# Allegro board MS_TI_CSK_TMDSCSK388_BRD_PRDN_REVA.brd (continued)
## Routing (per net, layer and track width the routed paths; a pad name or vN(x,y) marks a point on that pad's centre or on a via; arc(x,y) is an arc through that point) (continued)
VCC_3V3: length 182
  TOP w0.102: 47.98,12.27 U7.T25 ; U7.M7 49.86,21.46 49.42,21.46 49.09,21.13 48.72,21.13 48.51,21.34 U7.R7
  TOP w0.152: U7.T28 U7.U27 ; U7.U27 U7.T26 ; U7.U27 47.32,11.34 47.02,11.64 47.02,11.8 v1(47.01,11.81) ; U7.W7 U7.Y7 U7.Y6 U7.W5 ; U7.W5 46.67,22.34 v1(46.95,22.05) ; U7.W5 U7.Y4 ; v1(48.41,11.64) 48.21,11.84 U7.T26 ; U7.T26 47.98,12.27 ; U7.T6 U7.R5 U7.T4 47.7,22.84 v1(47.52,22.66) ; U7.D16 U7.E17 U7.F16 ; U7.M4 U7.L5 U7.M6 U7.M7 50.3,21.02 50.3,20.66 U7.N10 ; U7.R7 U7.T7
  TOP w0.178: R60.1 53.6,32.42 v1(52.94,32.42) ; v1(59.49,39.37) C35.1 60.2,39.99 60.22,40.01 U3.19
  TOP w0.203: v1(39.09,52.62) 38.44,51.98 U1.N7
  TOP w0.254: C45.1 62.72,31.31 62.89,31.15 R62.1 63.58,31.26 63.1,31.75 v1(63.1,31.85) ; C45.1 61.84,31.31 v1(61.78,31.37) ; C45.1 62.47,31.82 62.51,31.86 U5.1 ; v1(53.85,17.28) 53.98,17.15 U7.D16 ; v1(51.46,49.02) 51.46,47.89 51.21,47.63 C23.1 50.81,47.63 50.78,47.6 U2.1 ; U7.R5 48.67,22.34 v1(48.92,22.1) ; C40.1 50.81,34.67 U4.16 ; R85.1 19.39,1.14 v1(14.19,6.34) ; v1(49.02,20.07) 49.24,19.84 U7.N10 U7.N11 ; U7.Y4 45.61,22.84 45.48,22.71 v1(45.49,22.71) ; v1(39.83,33.45) 39.43,33.06 39.43,31.64 39.08,31.29 R59.1 ; U7.T7 48.01,21.37 48.01,21.81 U7.T6 ; v1(49.49,22.71) 49.62,22.84 U7.M4 ; U7.U25 U7.T25
  TOP w0.305: C20.1 v1(50.83,50.67) ; C15.1 v1(50.83,53.09)
  TOP w0.381: R44.1 45.09,36.04 v1(45.09,36.42) ; v1(64.2,27.84) 64.2,26.91 63.31,26.02 R69.1 ; U9.3 68.39,6.61 68,6.22 v1(66.98,6.22) 67.09,6.33 U9.1 ; R42.1 v1(49.33,35.72) 49.73,36.12 U4.16 ; v1(39.83,33.45) 40.09,33.71 R55.1 ; R70.1 R67.1 16.33,26.5 15.65,27.18 v1(14.76,27.18) ; R20.1 57.71,40.43 58.04,40.09 v1(58.04,39.46) 57.79,39.46 R35.1 ; U10.4 37.13,2.45 C67.1 37.13,2.41 R85.1 ; R45.1 v1(47.04,36.42) ; R7.1 v1(28.1,58.04) ; R24.1 47.34,40.57 v1(47.34,40.83) ; C40.1 v1(51.5,34.66) ; R10.1 v1(49.9,49.13) ; MOD1.46 51.38,52.39 51.38,52.39 C15.1 ; R25.1 v1(49.7,40.11) ; R84.1 v1(43.84,0.76) ; C20.1 51.47,51.37 51.78,51.69 MOD1.47 ; v1(41.45,3.05) 41.45,3.08 42.07,3.7 U11.5 ; R29.1 v1(41.13,37.76) 41.13,36.32 R40.1 ; R43.1 v1(43.87,36.42) ; R23.1 v1(42.63,40.83) ; R26.1 v1(44.15,40.82) ; R57.1 v1(66.32,33.22) ; R22.1 v1(45.75,40.84)
  L03_SIG1 w0.102: v1(53.85,17.28) 53.85,17.17 54.14,16.87 55.26,16.87 55.46,17.08
  L03_SIG1 w0.254: 56.29,17.91 56.46,17.91 v1(57.34,18.78)
  L03_SIG1 w0.305: 56.29,17.91 55.46,17.08
  L04_PWR1 w0.305: v1(47.52,22.66) 47.64,22.66 48,23.01 48,26.36 50.14,28.5 50.14,29.39 47.91,31.62 47.91,33.4 47.4,33.91 40.29,33.91 v1(39.83,33.45)
  L05_PWR2 w0.381: 43.84,1.32 43.84,1.31 v1(43.84,0.76)
  L06_SIG2 w0.178: v1(51.5,34.66) 51.5,33.86 v1(52.94,32.42)
  L06_SIG2 w0.254: v1(47.68,53.26) 45.94,54.99 42.6,54.99 40.23,52.62 v1(39.09,52.62)
  BOTTOM w0.178: C80.1 35.9,40.46 U13.39 ; R118.2 57.22,18.67 v1(57.34,18.78) ; C100.1 48.26,22.93 47.99,22.66 v1(47.52,22.66) ; C82.1 36.4,37.85 36.51,37.96 U13.34 ; C81.1 36.17,39.46 U13.37 ; v1(57.21,8.54) 56.67,8 R130.1 56.53,8.61 56.45,8.69 56.45,10.28 R121.1 ; v1(28.31,27.39) 28.52,27.6 28.52,28.77 29.85,30.1 R103.1 ; v1(60.47,36.99) 60.48,36.98 C83.1 61.37,38.38 61.41,38.41 v1(61.41,38.88) ; U12.1 47.82,56.87 C69.1 47.86,57.5 v1(47.8,57.56)
  BOTTOM w0.203: C177.1 54.28,9.68 C176.1 ; C177.1 53.5,9.65 C178.1 ; C177.1 54.26,10.03 v1(54.52,10.3) ; C114.1 49.46,20.02 49.07,20.02 v1(49.02,20.07)
  BOTTOM w0.254: v1(39.09,52.62) 38.73,52.26 R95.1 R96.1 ; v1(53.17,28.02) 52.88,28.31 C91.1 ; v1(41.13,37.76) 40.62,37.76 40.36,38.02 38.97,38.02 38.91,37.96 U13.34 ; v1(41.45,3.05) C189.1 ; v1(45.49,22.71) 45.67,22.71 45.97,23 45.97,23.91 C103.1 C102.1 ; U13.12 v1(58.04,39.46)
  BOTTOM w0.305: C100.1 C101.1 C102.1
  BOTTOM w0.381: v1(35.89,37.13) 35.82,37.06 35.59,37.06 35.83,37.3 C82.1 C81.1 C80.1 ; R91.1 46.41,53.26 v1(47.68,53.26) ; v1(41.05,6.99) 41.29,7.22 R131.1 ; C181.1 v1(66.98,6.22)
  vias: v1(13.36,20.83) v1(13.36,20.19) v1(13.36,19.56) v1(13.42,19.03) v1(13.92,19.61) v1(13.95,19.03) v1(14.46,19.61) v1(14.48,19.03) v1(35.89,36.49)
VCC_5V0: length 39
  TOP w0.203: U1.D8 32.05,53.06 31.27,53.83 ; U1.L1 v2(36.6,47.1)
  TOP w0.254: U1.N3 38.05,49.53 39.73,49.53 39.93,49.33 40.72,49.33 ; U1.A5 U1.B6 ; U1.A5 29.87,50.9 29.54,50.9 ; U1.A5 29.08,50.68 28.81,50.95
  TOP w0.305: U1.E8 32.7,53.21
  TOP w0.381: Q4.8 v1(22.93,36.53) ; 32.7,53.21 v1(32.7,54.54) ; v1(24.54,51.05) 24.76,51.27 C16.1 ; v1(29.87,57.15) 30.34,57.15 C6.1 30.64,56 31.27,55.36 31.27,53.83 ; v1(40.16,50.04) 40.73,49.47 C22.1 40.72,49.33 40.54,49.15 v1(40.54,48.64)
  L03_SIG1 w0.254: v2(36.6,47.1) 37.78,48.28 39.55,48.28 39.91,48.64 v1(40.54,48.64)
  BOTTOM w0.203: U14.12 25.4,34.7 25.05,35.05 C42.1
  BOTTOM w0.254: v1(32.7,54.54) 34.22,54.54 35.21,53.55 R94.1 ; v2(36.6,47.1) 36.32,46.83 C78.1
  BOTTOM w0.381: J4.87 18.26,40.33 18.32,40.39 v1(19.08,40.39) v1(19.84,40.39) v1(20.6,40.39) v1(21.24,40.39) ; C42.1 23.88,35.58 v1(22.93,36.53) ; R88.1 v1(46.28,51.88)
  vias: v1(9.48,56.21) v1(9.48,55.2) v1(9.48,54.18) v1(9.48,53.16) v1(10.11,56.72) v1(10.11,55.7) v1(10.11,54.69) v1(10.11,53.67) v1(19.08,39.62) v1(19.84,41.15) v1(19.84,39.62) v1(20.6,41.15) v1(20.6,39.62) v1(21.24,41.15) v1(21.24,39.62) v1(23.91,51.82) v1(23.91,51.05) v1(24.54,51.82)
VCC_CAM: length 104.3
  TOP w0.152: U7.D12 U7.E13 U7.F12
  TOP w0.254: v1(53.79,19.31) 53.98,19.12 U7.D12 ; U7.G13 U7.G12 52.52,18.8 52.93,18.8 U7.F12
  L04_PWR1 w0.381: v1(68.42,14.04) 67.48,14.99 64.42,14.99 62.4,17 61.86,17 61.25,16.4 v1(61.25,16.26)
  L05_PWR2 w0.381: v1(68.42,14.04) 67.85,13.47 67.85,11.56 60.86,4.57 50.38,4.57 49.55,3.74 41.39,3.74 41.03,3.39 20.65,3.39 11.47,12.56 11.47,22.46 11.21,22.73 9.68,22.73 v1(9.05,23.37) ; v1(53.79,19.31) 53.79,19.14 54.26,18.67 56.16,18.67 56.67,18.16 59.35,18.16 v1(61.25,16.26)
  BOTTOM w0.203: v1(53.79,19.31) 53.94,19.16 C118.1 53.95,18.67 R118.1
  BOTTOM w0.254: v1(9.05,23.37) 10.09,22.33 J4.22
VDD_DDR: length 76.8
  TOP w0.102: 22.32,23.75 22.35,23.72
  TOP w0.152: U7.AH16 U7.AG15 U7.AF16 ; v1(43.33,17.8) 43.48,17.66 U7.AE15 U7.AE16 U7.AF16 ; v1(42.78,16.38) 42.78,16.64 U7.AF16
  TOP w0.178: U6.D2 v1(32.31,22.55) ; C51.1 27.32,24.62 26.53,23.84 26.53,23.29 26.72,23.1 26.72,22.56 v1(26.71,22.55)
  TOP w0.254: v1(44.99,18.37) 44.98,18.36 U7.AB14 ; U7.AB17 U7.AC17 U7.AC18 U7.AB18 U7.AB17 ; U7.AB17 44.98,16.79 v1(44.95,16.81) 44.98,16.84 U7.AB15 ; U7.AB14 44.94,17.8 v1(44.47,17.8) 44.48,17.8 U7.AC15 U7.AB15 ; U7.AB14 U7.AB15
  TOP w0.381: v1(23.02,33.45) 23.02,32.87 v1(27.59,28.3) ; U6.K8 v1(26.71,16.95) ; U8.F1 v1(30.71,13.19) ; U6.B2 v1(33.91,22.55) ; U8.R1 v1(22.71,13.19) ; U8.H9 v1(29.11,5.99) ; U6.H2 v1(29.11,22.55) ; U6.C9 v1(33.11,16.15) ; U6.K2 v1(26.71,22.55) ; U8.A8 v1(34.71,6.79) ; U6.C1 v1(33.11,23.35) ; R72.1 22.16,23.91 22.32,23.75 ; U8.B2 v1(33.91,12.39) ; U8.K8 v1(26.71,6.79) ; U8.R9 v1(22.71,5.99) ; U8.G7 v1(29.51,8.63) ; U6.D9 v1(32.31,16.15) ; C53.1 22.35,23.72 v1(22.71,23.35) U6.R1 ; U6.H9 v1(29.11,16.15) ; U6.N9 v1(24.31,16.15) ; U8.N1 v1(24.31,13.19) ; U8.K2 v1(26.71,12.39) ; U8.D2 v1(32.31,12.39) ; U6.R9 v1(22.71,16.15) ; C52.1 24.41,24.66 24.31,24.57 v1(24.31,23.35) U6.N1 ; U8.C1 v1(33.11,13.19) ; U8.N9 v1(24.31,5.99) ; U8.A1 v1(34.71,13.19) ; U6.A8 v1(34.71,16.95) ; U6.F1 v1(30.71,23.35) ; U8.C9 v1(33.11,5.99) ; U8.D9 v1(32.31,5.99) ; U8.H2 v1(29.11,12.39) ; U8.E9 v1(31.51,5.99) ; U6.G7 v1(29.51,18.85) ; U6.E9 v1(31.51,16.15) ; U6.A1 v1(34.71,23.35)
  L05_PWR2 w0.178: v1(32.31,22.55) v1(33.11,23.35)
  BOTTOM w0.178: U14.2 26.2,29.67 C93.1 27.54,29.24 27.72,29.07 27.72,28.42 v1(27.59,28.3) ; v2(38.43,15.9) C141.1
  BOTTOM w0.203: U14.9 23.72,32.72 23.02,33.43 v1(23.02,33.45) ; C128.2 42.88,16.48 v1(42.78,16.38) ; v1(44.99,18.37) 44.99,18.37 C122.1 C121.2
  BOTTOM w0.254: C127.1 44.45,17.79 v1(44.47,17.8) ; C135.1 34.88,16.79 v1(34.71,16.95) ; C182.1 34.9,6.61 v1(34.71,6.79)
  BOTTOM w0.381: C184.1 29.26,5.85 v1(29.11,5.99) ; C147.1 22.74,16.12 v1(22.71,16.15) ; C185.1 27.35,6.15 v1(26.71,6.79) ; C107.1 35.12,23.35 v1(34.71,23.35) ; v1(33.11,13.19) 33.19,13.27 C162.1 ; v1(29.11,16.15) 29.25,16.02 29.25,15.85 29.38,15.71 C144.1 ; v1(24.31,13.19) 24.81,13.69 C165.1 ; v1(26.71,12.39) 27.35,13.03 C173.1 ; C188.1 22.62,5.89 v1(22.71,5.99) ; v1(33.11,23.35) 33.07,23.4 C105.1 ; v1(33.11,16.15) 33.19,16.07 C143.1 ; v1(26.71,16.95) 27.48,16.19 C145.1 ; C170.1 35.34,13.1 34.81,13.1 v1(34.71,13.19) ; v1(24.31,5.99) 24.52,5.78 C187.1 ; C146.1 24.65,15.59 24.31,15.92 v1(24.31,16.15) ; C163.1 31.29,13.77 v1(30.71,13.19) ; C104.1 30.88,23.91 30.87,23.9 30.87,23.68 30.83,23.64 30.83,23.47 v1(30.71,23.35) ; v1(22.71,13.19) 22.87,13.35 C166.1 ; v1(29.11,22.55) 29.1,22.54 C98.1 ; v1(33.11,5.99) 33.07,5.94 C183.1
  vias: v1(34.15,28.94) v1(34.4,29.45) v1(34.91,28.94) v1(35.17,29.45) v1(35.67,28.94) v1(35.93,29.45) v1(36.44,28.94)
VDD_DDR_VREF: length 67.2
  TOP w0.102: v2(39.35,16.01) 39.81,16.01 39.98,15.84 U7.AL18
  TOP w0.381: U8.M8 v1(25.11,6.79) ; U6.H1 v1(29.11,23.35) ; U6.M8 v1(25.11,16.95) ; U8.H1 v1(29.11,13.19)
  L04_PWR1 w0.381: v1(25.11,6.79) 25.11,9.78 25.48,10.15 27.36,10.15 28.19,10.97 28.19,12.26 v1(29.11,13.19) ; v1(29.11,13.19) 31.14,15.21 38.55,15.21 v2(39.35,16.01) 39.35,16.61 38.43,17.53 36.25,17.53 33.71,20.07 28.73,20.07 28.35,20.45 28.35,22.59 v1(29.11,23.35) 29.11,23.92 27.99,25.05 25.27,25.05 v1(22.67,27.64) ; v1(29.11,13.19) 28.71,13.6 28.47,13.6 v1(25.11,16.95)
  BOTTOM w0.178: U14.5 24.75,30.82 24.52,31.06 24,31.06 23.51,30.56 23.51,30.49 23.17,30.15 C90.1
  BOTTOM w0.203: C132.2 39.88,16.09 39.81,16.01 v2(39.35,16.01)
  BOTTOM w0.381: v1(22.67,27.64) 22.31,28 22.31,29.27 22.69,29.65 C90.1 ; C106.1 29.11,23.8 v1(29.11,23.35) ; C186.1 26.43,5.48 v1(25.11,6.79) ; v1(29.11,13.19) 29.38,13.46 C164.1 ; v1(25.11,16.95) 25.52,16.55 25.58,16.55 26.55,15.58 C142.1
VDDR_VTT: length 22.7
  TOP w0.254: C50.2 17.17,19.57 18.15,19.57 18.32,19.4 RA4.2
  TOP w0.381: RA4.1 RA4.2 RA4.3 RA4.4 ; v1(18.38,15.4) 18.28,15.29 17.71,15.29 17.16,15.84 C49.2 C50.2
  L06_SIG2 w0.254: v1(24.49,30.35) 25,30.35 25.38,30.73 v1(27.33,30.73)
  BOTTOM w0.178: U14.1 27.24,30.82 v1(27.33,30.73) ; C92.1 25.8,29.46 U14.3
  BOTTOM w0.254: v1(21.34,27.39) 21.53,27.2 C97.2
  BOTTOM w0.381: C92.1 25.56,29.22 C94.1 24.46,30.33 v1(24.49,30.35) v1(23.98,30.35) ; v1(18.46,12.62) C169.2 C154.2 18.46,15.32 v1(18.38,15.4) 18.38,15.67 18.51,15.8 18.51,16.15 RA11.1 RA11.2 RA11.3 RA11.4
  vias: v1(19.14,15.68)
BB_PMIC_3V3: length 2.7
  TOP w0.381: R27.2 12.86,40.39 v1(12.09,41.15)
  BOTTOM w0.381: v1(11.33,41.15) 11.27,41.09 J4.88
  vias: v1(10.57,41.91) v1(10.57,41.15) v1(11.33,41.91) v1(12.09,41.91)
BB_VCC3V3: length 1.7
  BOTTOM w0.254: v1(10.52,21.72) 10.63,21.83 J4.20 12.13,21.83
  vias: v1(8.61,21.72) v1(8.61,21.08) v1(9.25,21.72) v1(9.25,21.08) v1(9.88,21.72) v1(9.88,21.08) v1(10.52,21.08)
CC_RST: length 62.4
  TOP w0.102: v1(42.49,5.42) 42.8,5.12 43.15,5.12 43.41,4.85 44.3,4.85 44.45,4.7 44.45,2.96 43.88,2.4
  TOP w0.14: U11.3 43.52,2.08 R84.2 43.88,2.4
  L06_SIG2 w0.102: 57.31,17.26 56.41,17.26 55.48,16.33 55.48,15.83 54.77,15.11 54.46,15.11 54,14.66 52.27,14.66 51.69,15.24 50.85,15.24 50.07,14.46 50.07,14.28 49.74,13.96 49.68,13.96 49.32,13.61 49.32,13.02 49.38,12.96 49.38,9.97 49.96,9.39 49.99,9.39 51.59,7.79
  L06_SIG2 w0.119: v1(70.87,29.19) 70.22,28.54 69.64,28.54 66.56,25.46 65.94,25.46 64.41,25.46 63.59,24.64 62,24.64 60.66,23.29 60.66,20.62 57.31,17.26 ; v1(42.49,5.42) 42.18,5.73 42.18,6.31 42.47,6.6 43.01,6.6 43.73,5.88 43.73,5.45 44.18,5 52.19,5 52.49,5.3 52.49,6.89 51.59,7.79
  BOTTOM w0.14: J3.54 69.41,27.73 v1(70.87,29.19)
CLK32OUT_PMIC: length 48.6
  TOP w0.14: R36.1 64.81,38.65 v1(64.52,38.35) ; R19.2 v1(28.35,41.93)
  L06_SIG2 w0.102: 35.97,46.3 35.15,47.12 32.89,47.12 32.07,46.3
  L06_SIG2 w0.119: 32.07,46.3 32.04,46.27 31.49,46.27 28.35,43.13 v1(28.35,41.93) ; 35.97,46.3 37.9,44.37 50.72,44.37 51.32,43.76 54.65,43.76 56.77,41.63 56.77,37.39 58.23,35.93 60.11,35.93 60.68,36.5 61.77,37.59 63.76,37.59 v1(64.52,38.35)
CLKIN32: length 5.7
  TOP w0.102: 41.48,7.79 U7.AJ31
  TOP w0.14: R82.2 39.97,5.59 40.05,5.68 41.15,5.68 41.5,6.03 41.5,7.77 41.48,7.79
CORE_CVDD: length 99.5
  TOP w0.102: 47.19,18.34 v1(47.25,18.28)
  TOP w0.254: U7.T17 U7.R17 ; U7.T17 U7.T18 ; U7.T17 U7.U17 ; U7.R17 U7.P17 48.98,16.81 v1(49.01,16.85) 48.98,16.88 U7.P15 U7.R15 v1(48.48,16.84) U7.R17 ; U7.Y19 U7.Y20 U7.W20 U7.W19 ; U7.Y19 U7.W19 ; U7.Y19 45.98,15.79 v1(45.94,15.83) ; U7.W13 46.48,18.85 v1(46.51,18.88) 46.55,18.84 U7.V12 ; U7.W13 47.19,18.34 46.98,18.55 U7.V12 ; U7.W13 U7.W14 ; U7.W13 U7.Y13 U7.Y14 U7.W14 ; U7.W14 46.48,17.39 v1(46.51,17.35) 46.96,17.35 U7.V15 ; U7.U17 U7.V17 46.98,16.8 v1(46.95,16.82) ; U7.U17 47.48,16.91 ; U7.V12 U7.U12 ; U7.V12 U7.V11 U7.U11 U7.U12 ; U7.U12 47.48,18.51 v1(47.25,18.28) 47.75,18.28 47.81,18.34 U7.T13 ; 47.48,16.91 U7.U15 U7.V15 ; 47.48,16.91 47.39,16.82 v1(46.95,16.82) ; U7.V15 46.98,16.88 46.95,16.86 v1(46.95,16.82) ; U7.W19 v1(46.84,15.34)
  L06_SIG2 w0.102: v1(49.01,16.85) 49.01,17.45 49.49,17.92 50.81,17.92 50.82,17.92 51.19,17.92 52.02,18.75 54.43,18.75 55.7,20.02 57.22,20.02 58.05,20.85 58.05,24.91 58.82,25.68 59.72,25.68 v1(60.02,25.99)
  BOTTOM w0.102: v1(48.48,16.84) 48.44,16.84 ; 48.11,16.52 C138.1 ; 47.44,16.33 C140.1 ; v1(60.02,25.99) 60.02,26.33 59.85,26.51 59.85,27.5 59.65,27.69 58.09,27.69 57.89,27.48 54.8,27.48 54.42,27.1 48.64,27.1 48.41,26.88 46.51,26.88 46.31,26.67 44.02,26.67 43.68,27.02 43.68,27.49 43.7,27.51 43.7,28.27 43.47,28.5 41.23,28.5 39.65,30.07 38.54,30.07 25.94,42.67 24.54,42.67 22.64,44.58 22.64,48.26 23.65,49.28 R141.2
  BOTTOM w0.203: v1(46.51,17.35) 46.51,17.2 46.26,16.94 C131.1 ; 48.44,16.84 48.11,16.52 ; C137.1 49.01,16.65 v1(49.01,16.85) 49.01,17.01 C125.1 ; 48.44,16.84 48.07,17.22 C126.1 ; C124.1 47.22,18.26 v1(47.25,18.28) ; C129.1 45.52,16.25 v1(45.94,15.83) 45.7,15.59 C153.1 ; v1(46.95,16.82) 47.44,16.33
  BOTTOM w0.254: v1(47.34,30.25) 47.37,30.27 C88.1
  vias: v1(18.83,42.55) v1(18.95,43.82) v1(18.95,43.18) v1(19.59,42.55) v1(20.35,42.55) v1(21.11,42.55) v1(21.49,43.82) v1(21.49,43.05)
CVDD_ARM: length 5.9
  TOP w0.254: v1(50.02,18.87) 49.98,18.83 U7.M13 U7.M14 ; U7.L17 U7.M17 49.98,15.87 50.01,15.84 v1(50.02,15.84) U7.L18 U7.L17 ; U7.L17 U7.K17
  BOTTOM w0.203: C151.1 50.4,15.51 50.07,15.84 v1(50.02,15.84) 49.86,15.68 49.86,15.47 C150.2 ; C113.1 50.07,19.41 50.07,18.92 v1(50.02,18.87) 50.02,18.72 49.74,18.44 C120.1
  vias: v1(23.78,42.29) v1(23.78,41.4)
CVDD_HDVICP: length 10.6
  TOP w0.102: 46.98,13.83 v1(46.99,13.82)
  TOP w0.152: U7.U21 47.4,14.26 47.4,13.87 47.32,13.79 47.01,13.79 v1(46.99,13.82) ; v1(45.97,13.31) 46.48,13.82 U7.W22
  TOP w0.254: U7.V21 U7.U21 U7.U20 U7.V20 U7.V21 ; U7.V21 46.98,13.83 46.96,13.84 U7.W22
  TOP w0.305: 40.66,40.7 40.83,40.7 C39.2
  TOP w0.381: v1(40.29,40.13) 40.29,40.29 40.58,40.58 R21.2 40.66,40.7 40.82,40.54 v1(40.82,40.13)
  L05_PWR2 w0.381: v1(46.99,13.82) 46.76,13.59 46.25,13.59 v1(45.97,13.31)
  BOTTOM w0.102: C41.1 44.96,13.45 45.11,13.31 45.29,13.31 45.3,13.3 45.61,13.3 45.62,13.31 v1(45.97,13.31)
  BOTTOM w0.203: v1(46.99,13.82) 46.99,13.82 C158.1 ; C168.1 46.27,13.31 v1(45.97,13.31)
DDR_PGOOD: length 76.1
  TOP w0.14: v1(27.18,27.31) 26.86,26.99 26.08,26.99 24.7,28.37 13.75,28.37 11.28,25.89 9.51,25.89 9.12,25.5 v1(8.34,25.5) ; U11.6 v1(40.84,4.28)
  L03_SIG1 w0.119: v1(8.34,25.5) 8.34,25.06 8,24.73 8,20.82 9.42,19.41 9.42,14.64 21.79,2.27 37.38,2.27 38.07,2.97 39.53,2.97 v1(40.84,4.28)
  BOTTOM w0.14: v1(27.18,27.31) 27.49,27.62 27.55,27.62 28.1,28.17 28.1,29.34 28.87,30.1 R103.2 28.68,30.14 27.89,30.94 27.89,31.23 27.59,31.52 U14.20
DM388_BT_EN: length 44.5
  TOP w0.102: U7.M1 50.25,24.61 50.25,24.61 50.7,25.06 51.23,25.06 52.09,25.92 52.09,26.74
  TOP w0.14: 52.09,26.74 52.09,28.43 53.1,29.45 53.43,29.45 54.37,30.38 54.37,32.63 54.14,32.86 54.14,35.6 55.55,37.01 55.55,37.97 55.99,38.41 55.99,40.54 55.46,41.06 50.65,41.06 50.42,41.3 v1(49.97,41.3)
  L03_SIG1 w0.119: v1(43.84,53.49) 45.34,53.49 47.61,51.22 47.61,42.89 49.2,41.3 v1(49.97,41.3)
  BOTTOM w0.14: U12.4 44.74,54.97 44.6,54.83 44.6,54.25 v1(43.84,53.49)
DM388_BTMODE[0]: length 48.1
  TOP w0.102: U7.W6 46.6,21.84 v1(46.95,21.48)
  TOP w0.14: v1(40.09,35.46) 40.09,35.03 40.82,34.3 40.9,34.3 41.45,33.74 R55.2
  L03_SIG1 w0.102: 51.71,26.59 51.57,26.45 51.57,25.73 51.26,25.42 50.35,25.42 48.51,23.58 48.51,21.64 48.1,21.23 48.1,20.6 47.75,20.25 47.19,20.25 47.13,20.31 46.95,20.31 46.57,20.69 46.57,21.1 v1(46.95,21.48)
  L03_SIG1 w0.119: 51.71,26.59 52.26,27.15 52.26,34.91 47.46,39.71 42.35,39.71 41.76,40.29 41.76,40.5 41.63,40.63 41.63,41.95 41.21,42.36 40.31,42.36 39.86,41.91 39.86,36.12 40.09,35.9 v1(40.09,35.46)
  BOTTOM w0.14: v1(40.09,35.46) 38.74,35.46 38.74,35.46 38.37,35.46 38.37,35.46 U13.29
DM388_BTMODE[1]: length 21.7
  TOP w0.102: v1(46.96,22.73) 46.85,22.84 U7.W4
  TOP w0.14: R46.1 40.9,35.01 40.51,35.4 40.51,35.63 40.19,35.96 v1(39.35,35.96)
  L03_SIG1 w0.119: v1(41.46,32.56) 40.87,33.15 40.87,33.76 39.35,35.28 v1(39.35,35.96)
  L06_SIG2 w0.102: 42.59,26.59 44.39,24.79 44.9,24.79 v1(46.96,22.73)
  L06_SIG2 w0.119: 42.59,26.59 42.36,26.82 42.36,28.33 42.15,28.55 42.15,31.87 v1(41.46,32.56)
  BOTTOM w0.14: U13.30 v1(39.35,35.96)
DM388_BTMODE[2]: length 34.9
  TOP w0.102: v1(46.95,23.32) 46.94,23.34 U7.W3
  TOP w0.14: SW1.2 38.28,39.4 39.2,38.47 R28.1 39.96,36.93 v1(40.42,36.46)
  L03_SIG1 w0.102: v1(46.95,23.32) 46.95,23.84 49.71,26.59
  L03_SIG1 w0.119: v1(40.42,36.46) 40.42,37.83 40.85,38.25 45.9,38.25 46.49,37.66 46.49,37.5 47.09,36.91 47.25,36.91 47.54,36.62 47.54,35.96 48.87,34.62 49.6,34.62 50.88,33.34 50.88,30.28 51.15,30.01 51.15,28.25 50.88,27.98 50.88,27.69 50.56,27.37 49.95,26.76 49.87,26.76 49.71,26.59
  BOTTOM w0.14: U13.31 v1(40.42,36.46)
DM388_BTMODE[3]: length 24.5
  TOP w0.102: U7.U2 47.48,24.58 49.49,26.59
  TOP w0.14: v1(41.81,36.96) 42.26,36.96 43.21,36.01 43.21,34.88 43.35,34.73 R43.2 43.91,34.73 44.46,34.18 44.46,33.42 44.46,33.42 44.46,32.68 45.13,32.01 45.13,31.35 45.13,31.35 45.13,31.11 46.75,29.49 49.65,29.49 50.4,28.75 50.4,27.5 49.49,26.59
  BOTTOM w0.14: U13.32 v1(41.81,36.96)
DM388_BTMODE[4]: length 39.8
  TOP w0.102: v1(46.95,20.85) 46.48,20.37 U7.W9
  TOP w0.14: v1(48.85,36.68) 48.4,36.68 47.92,37.16 47.92,38.3 48.76,39.13 R33.1
  L03_SIG1 w0.102: 51.32,26.59 50.64,25.92 50.37,25.92 48.32,23.86 48.32,23.84 48.31,23.83 48.31,21.98 47.91,21.58 47.91,21.32 47.9,21.32 47.9,20.69 47.68,20.47 47.67,20.47 47.66,20.46 47.35,20.46 v1(46.95,20.85)
  L03_SIG1 w0.119: v1(48.85,36.68) 50.04,36.68 51.56,35.15 51.7,35.15 52.04,34.82 52.04,27.89 51.97,27.82 51.97,27.24 51.32,26.59
  BOTTOM w0.14: v1(48.85,36.68) 45.21,40.31 43.85,40.31 42.75,41.41 42.75,41.92 42.46,42.21 42.04,42.21 41.15,41.32 38.51,41.32 38.37,41.46 U13.41
DM388_BTMODE[5]: length 36.3
  TOP w0.102: U7.T5 47.79,22.34 v1(47.51,22.06)
  TOP w0.14: v1(40.25,41.75) 40.25,42.61 41.46,43.82 R16.1
  L03_SIG1 w0.102: 50.55,26.59 50.28,26.32 50.18,26.32 47.9,24.04 47.9,22.45 v1(47.51,22.06)
  L03_SIG1 w0.119: 50.55,26.59 51.42,27.47 51.42,27.9 51.6,28.07 51.6,30.19 51.39,30.4 51.39,33.46 49.62,35.23 49.27,35.23 48.09,36.41 48.09,37.54 46.19,39.44 42.31,39.44 41.54,40.2 41.54,40.4 41.4,40.54 41.4,41.85 41.12,42.14 40.64,42.14 v1(40.25,41.75)
  BOTTOM w0.14: v1(40.25,41.75) 38.59,41.75 38.37,41.96 U13.42
DM388_BTMODE[6]: length 33
  TOP w0.102: U7.T3 47.64,23.34 v1(47.52,23.21)
  TOP w0.14: v1(40.96,41.75) 41.28,42.06 41.28,42.54 41.39,42.65 R18.1
  L03_SIG1 w0.102: 50.17,26.59 47.52,23.95 v1(47.52,23.21)
  L03_SIG1 w0.119: 50.17,26.59 51.15,27.58 51.15,27.94 51.38,28.16 51.38,30.1 51.15,30.32 51.15,33.38 49.59,34.95 49.24,34.95 47.82,36.37 47.82,37.5 46.15,39.17 42.27,39.17 41.32,40.11 41.32,40.31 40.96,40.67 v1(40.96,41.75)
  BOTTOM w0.14: v1(40.96,41.75) 40.54,42.17 39.61,42.17 39.56,42.12 38.71,42.12 38.37,42.46 U13.43
DM388_BTMODE[7]: length 31.6
  TOP w0.102: 49.9,26.59 49.61,26.3 49.48,26.3 48.07,24.89 48.07,24.83 47.68,24.44 47.68,24.14 U7.T2
  TOP w0.14: v1(43.34,41.43) 43.34,39.35 43.13,39.13 43.03,39.13 ; R31.1 43.03,39.13 ; 43.03,39.13 43.34,38.83 43.34,37.47 43.87,36.93 44.16,36.93 44.46,36.63 44.46,35.02 44.77,34.71 44.77,33.32 44.75,33.3 44.75,32.8 45.43,32.13 45.43,31.23 46.89,29.77 49.95,29.77 50.64,29.08 50.64,27.34 50,26.69 50,26.69 49.9,26.59
  BOTTOM w0.14: v1(43.34,41.43) 43.04,41.72 43.04,42.04 42.58,42.51 42.26,42.51 41.64,43.12 38.63,43.12 38.47,42.96 U13.44
DM388_BTMODE[8]: length 26
  TOP w0.102: 50.24,26.59 49.74,26.1 49.57,26.1 48.27,24.8 48.27,24.64 U7.T1
  TOP w0.14: R50.1 46.01,34.73 46.14,34.6 46.14,33.38 45.96,33.19 v1(45.96,33.16) 45.96,31.91 47.12,30.75 49.65,30.75 50.88,29.52 50.88,27.24 50.24,26.59
  BOTTOM w0.14: v1(45.96,33.16) 45.96,34.26 45.66,34.56 40.58,34.56 40.49,34.47 39.68,34.47 39.59,34.56 38.74,34.56 38.21,34.03 37.53,34.03 U13.26
DM388_BTMODE[9]: length 32.4
  TOP w0.102: v1(47.53,21.48) 47.53,21.4 47.98,20.94 U7.T8
  TOP w0.14: v1(50.22,35.36) 49.6,34.74 R48.1
  L03_SIG1 w0.102: v1(47.53,21.48) 48.1,22.06 48.1,23.96 50.27,26.12 50.46,26.12 50.94,26.59
  L03_SIG1 w0.119: 50.94,26.59 51.7,27.35 51.7,27.86 51.82,27.98 51.82,33.56 51.23,34.14 50.53,34.84 50.53,35.05 v1(50.22,35.36)
  BOTTOM w0.14: U13.27 38.23,34.46 38.62,34.85 38.77,34.85 38.78,34.86 39.7,34.86 39.8,34.77 40.37,34.77 40.47,34.86 49.73,34.86 v1(50.22,35.36)
DM388_BTMODE[10]: length 41.9
  TOP w0.102: v1(48.93,21.51) 48.92,21.51 48.92,21.51 48.81,21.51 48.49,21.84 U7.R6
  TOP w0.14: v1(47.63,41.53) 47.91,41.24 47.91,39.4 47.65,39.13 R24.2
  L03_SIG1 w0.102: v1(48.93,21.51) 49.48,21.51 49.88,21.91 49.88,23.74 51.15,25.01 51.44,25.01 52,25.57 52,26.12 52.47,26.59
  L03_SIG1 w0.119: 52.47,26.59 52.78,26.9 52.78,30.89 52.98,31.09 53.22,31.09 53.43,31.29 53.43,34.58 52.04,35.97 51.9,35.97 48.42,39.45 48.42,40.74 v1(47.63,41.53)
  L06_SIG2 w0.119: v1(47.63,41.53) 47.19,41.53 43.37,37.71 43.37,37.12 v1(43.06,36.81)
  BOTTOM w0.14: U13.28 38.31,34.96 38.5,35.15 38.56,35.15 38.57,35.16 39.82,35.16 39.92,35.06 40.25,35.06 40.35,35.16 40.59,35.16 40.85,35.16 42.5,36.81 v1(43.06,36.81)
DM388_BTMODE[11]: length 37.8
  TOP w0.102: v1(48.93,22.72) 48.81,22.84 U7.R4
  TOP w0.14: v1(52.94,31.78) 52.94,31.35 53.04,31.24 53.76,31.24 R60.2
  L06_SIG2 w0.102: v1(48.93,22.72) 48.56,23.09 48.56,23.45 48.99,23.88 51.64,23.88 51.73,23.79 53.29,23.79 56.03,26.53 56.03,26.59
  L06_SIG2 w0.119: 56.03,26.59 56.07,26.63 56.07,28.27 55.65,28.69 55.65,30.16 55.29,30.52 54.69,30.52 53.43,31.78 v1(52.94,31.78) 52.51,31.78 49.65,34.63 42.84,34.63 40.01,37.46 v1(39.2,37.46)
  BOTTOM w0.14: v1(52.94,31.78) 52.94,31.44 53.12,31.26 R60.2 ; v1(39.2,37.46) 38.45,37.46 38.45,37.46 U13.33
DM388_BTMODE[12]: length 33.9
  TOP w0.102: v1(48.94,23.29) 48.89,23.34 U7.R3
  TOP w0.14: v1(42.02,40.79) 42.02,40.31 41.16,39.45 R29.2
  L03_SIG1 w0.102: 52.09,26.59 51.77,26.27 51.77,25.63 51.35,25.21 50.43,25.21 48.94,23.72 v1(48.94,23.29)
  L03_SIG1 w0.119: v1(42.02,40.79) 42.02,40.35 42.39,39.98 47.5,39.98 51.79,35.69 51.93,35.69 52.51,35.11 52.51,27.02 52.09,26.59
  BOTTOM w0.14: v1(42.02,40.79) 41.56,40.79 41.32,41.04 38.45,41.04 38.37,40.96 U13.40
DM388_BTMODE[13]: length 31.5
  TOP w0.102: U7.R2 48.49,23.84 48.77,24.13 48.77,24.3 48.79,24.32 48.79,24.62 49.81,25.64 50.07,25.64 50.96,26.53 51.22,26.53 51.36,26.67
  TOP w0.14: v1(45.16,41.38) 45.16,37.54 46.45,36.24 46.45,35.28 47.01,34.73 R45.2 47.08,34.73 47.64,34.18 47.64,32.98 47.61,32.95 47.61,31.61 47.92,31.29 50.12,31.29 51.36,30.05 51.36,26.67
  BOTTOM w0.14: U13.45 42.47,43.46 44.56,41.38 v1(45.16,41.38)
DM388_BTMODE[14]: length 32
  TOP w0.102: U7.R1 48.48,24.72 49.6,25.84 49.91,25.84 50.66,26.59
  TOP w0.14: 44.69,39.12 44.74,39.12 44.86,39 44.86,37.42 46.16,36.12 46.16,35.02 46.45,34.73 46.45,31.83 47.24,31.04 49.94,31.04 51.12,29.86 51.12,27.05 50.66,26.59 ; 44.69,39.12 R26.2 ; 44.69,39.12 44.83,39.27 44.83,40.97 44.48,41.33 v1(44.48,42.37)
  BOTTOM w0.14: v1(44.48,42.37) 42.89,43.96 U13.46
DM388_BTMODE[15]: length 33.6
  TOP w0.102: U7.P2 48.98,24.22 48.99,24.24 48.99,24.54 49.88,25.43 50.19,25.43 51.03,26.26
  TOP w0.14: 46.24,39.15 46.66,38.72 46.66,37.35 47.08,36.93 47.09,36.93 47.1,36.92 47.36,36.92 47.93,36.35 47.93,32.75 47.9,32.72 47.9,31.73 48.06,31.57 50.19,31.57 51.6,30.16 51.6,26.4 51.46,26.26 51.03,26.26 ; 46.24,39.15 46.44,39.35 v1(46.44,41.4) ; 46.24,39.15 R30.1
  BOTTOM w0.14: U13.47 40.8,44.46 40.87,44.39 41.29,44.39 41.36,44.46 43.38,44.46 v1(46.44,41.4)
DM388_CAM_DAT0: length 42.5
  TOP w0.102: 53.77,26.59 53.77,26.56 54.09,26.24 54.43,26.24 54.77,25.9 54.77,24.14 U7.C2
  TOP w0.14: v1(55.04,29.25) 55.04,28.72 54.47,28.16 53.97,28.16 53.74,27.93 53.74,26.63 53.77,26.59
  L03_SIG1 w0.119: v1(55.04,29.25) 55.04,29.5 54.56,29.98 54.56,30.2 54.18,30.58 54.18,34.88 54.61,35.31 56.05,35.31 56.55,35.8 56.55,35.97 56.11,36.41 56.11,36.58 56.28,36.75 56.45,36.75 56.89,36.31 57.06,36.31 57.22,36.48 57.22,36.65 56.79,37.08 56.79,37.25 56.96,37.42 57.13,37.42 57.56,36.98 57.73,36.98 57.87,37.12 57.87,37.63 57.99,37.75 62.72,37.75 63.25,37.22 63.48,37.22 64.5,37.22 65.76,38.48 68.32,38.48 69.48,39.64 69.81,39.64 70.18,39.26 70.18,39.02 70.34,38.86 71.27,38.86 71.91,39.5 71.91,40.33 72.42,40.84 73.83,40.84 v1(74.26,41.26)
  BOTTOM w0.14: v1(74.26,41.26) 73.79,41.73 J3.1
DM388_CAM_DAT1: length 41.7
  TOP w0.102: 53.46,26.59 53.48,26.58 53.48,26.57 54.01,26.04 54.35,26.04 54.48,25.91 U7.C1
  TOP w0.14: 53.46,26.59 52.68,27.38 52.68,27.77 52.68,28.19 53.25,28.76 53.75,28.76 v1(54.4,29.41)
  L03_SIG1 w0.119: v1(73.39,41.23) 72.26,41.23 71.41,40.38 69.91,40.38 69.21,39.68 66,39.68 65.71,39.39 65.71,38.81 64.39,37.49 63.37,37.49 62.83,38.03 56.27,38.03 56.09,37.85 56.09,37.06 55.91,36.88 53.6,36.88 53.45,36.73 53.45,36.49 53.57,36.37 55.31,36.37 55.43,36.25 55.43,36.01 55.31,35.89 54.03,35.89 53.91,35.77 53.91,30.47 54.34,30.04 54.34,29.89 54.39,29.84 54.39,29.42 v1(54.4,29.41)
  BOTTOM w0.14: J3.3 73.38,41.23 v1(73.39,41.23)
DM388_CAM_DAT2: length 41.5
  TOP w0.102: 55.45,26.63 55.45,26.21 54.99,25.75 54.99,24.23 54.98,24.22 U7.B2
  TOP w0.14: v1(55.05,30.1) 55.45,29.7 55.45,26.63
  L03_SIG1 w0.119: v1(75.26,39.73) 75.26,40.5 75.14,40.62 73.72,40.62 72.51,40.62 72.13,40.24 72.13,39.41 71.37,38.64 70.7,38.64 70.3,38.24 65.87,38.24 65.14,37.52 65.14,36.87 64.91,36.64 63.64,36.64 62.96,36.64 62.12,37.48 59.86,37.48 58.65,36.28 57.34,36.28 56.01,34.95 56.01,34.49 55.84,34.32 55.34,34.32 55.22,34.44 55.22,34.88 55.08,35.03 54.64,35.03 54.45,34.84 54.45,30.69 v1(55.05,30.1)
  BOTTOM w0.14: v1(75.26,39.73) 74.26,40.73 J3.5
DM388_CAM_DAT3: length 41.5
  TOP w0.102: 55.71,26.09 55.2,25.58 55.2,24.1 55.46,23.84 U7.A2
  TOP w0.14: v1(55.1,30.96) 55.71,30.35 55.71,26.09
  L03_SIG1 w0.119: v1(55.1,30.96) 55.54,30.96 55.63,31.06 55.63,31.57 55.53,31.67 54.93,31.67 54.78,31.83 54.78,32.81 55.12,33.14 55.12,33.31 54.84,33.59 54.84,33.76 55.01,33.92 55.18,33.92 55.45,33.65 55.62,33.65 55.99,34.01 56.16,34.01 56.39,33.78 56.56,33.78 56.73,33.94 56.73,34.11 56.34,34.5 56.34,34.67 56.51,34.84 56.68,34.84 57.07,34.45 57.24,34.45 57.41,34.62 57.41,34.79 57.02,35.18 57.02,35.35 57.14,35.47 57.34,35.47 57.74,35.08 57.92,35.08 58.07,35.24 58.07,35.4 57.76,35.71 57.76,35.88 57.87,35.98 60.5,35.98 61.34,36.83 62.23,36.83 62.68,36.38 65.25,36.38 65.36,36.5 65.36,37.43 65.93,37.99 70.46,37.99 70.88,38.42 71.46,38.42 71.62,38.58 72.38,38.58 72.5,38.7 72.5,40.11 72.61,40.23 72.85,40.23 72.95,40.12 72.95,39.5 73.05,39.4 73.46,39.4 73.56,39.5 v1(73.56,40.23)
  BOTTOM w0.14: J3.7 v1(73.56,40.23)
DM388_CAM_DAT4: length 41.5
  TOP w0.102: 55.98,26.62 55.98,26.12 56.19,25.91 56.19,24.05 U7.A3
  TOP w0.14: 55.98,26.62 55.98,30.68 55.2,31.46 v1(55.2,32.16)
  L03_SIG1 w0.119: v1(55.2,32.16) 55.2,32.84 55.75,33.39 56.55,33.39 57.69,34.52 58.25,34.52 58.37,34.64 58.37,35.57 58.48,35.69 58.72,35.69 58.84,35.57 58.84,34.64 58.96,34.52 59.2,34.52 59.32,34.64 59.32,35.57 59.44,35.69 59.68,35.69 59.8,35.57 59.8,34.64 59.92,34.52 60.16,34.52 60.36,34.72 60.36,35.48 61.42,36.54 62.18,36.54 62.31,36.41 62.55,36.16 65.47,36.16 65.59,36.28 65.59,37.34 66.02,37.77 70.67,37.77 71.09,38.2 71.75,38.2 71.82,38.27 72.95,38.27 73.2,38.53 75.02,38.53 75.13,38.63 75.13,39.31 74.71,39.73 v1(74.2,39.73)
  BOTTOM w0.14: J3.9 v1(74.2,39.73)
DM388_CAM_DAT5: length 41.8
  TOP w0.102: U7.B4 55.81,22.84 56.62,23.65 56.62,26.66
  TOP w0.14: v1(55.91,33) 56.36,33 56.8,32.56 56.8,30.15 56.66,30.02 56.66,28.79 56.62,28.74 56.62,26.66
  L03_SIG1 w0.119: v1(74.2,37.73) 73.79,37.31 72.88,37.31 72.76,37.19 72.76,37 72.64,36.87 72.4,36.87 72.29,36.98 72.29,37.95 72.19,38.05 71.91,38.05 71.81,37.95 71.81,36.93 71.7,36.82 66.68,36.82 66.36,37.14 66.03,37.14 65.81,36.92 65.81,36.09 65.66,35.94 62.46,35.94 62.09,36.32 61.51,36.32 60.58,35.39 60.58,34.39 60.46,34.27 57.75,34.27 56.79,33.3 56.79,31.28 56.67,31.16 56.03,31.16 55.91,31.28 v1(55.91,33)
  BOTTOM w0.14: J3.13 73.7,38.23 v1(74.2,37.73)
DM388_CAM_DAT6: length 41.3
  TOP w0.102: v1(54.48,23.29) 54.48,22.81 54.48,22.81 U7.C5
  L03_SIG1 w0.102: 58.58,28.04 57.97,27.44 57.97,27.11 56.7,25.83 56.7,23.85 56.14,23.29 v1(54.48,23.29)
  L03_SIG1 w0.119: 58.58,28.04 58.58,28.63 60.77,30.82 64.58,30.82 64.7,30.94 64.7,31.67 65.11,32.08 66.55,32.08 68.79,29.85 68.79,28.62 68.91,28.5 70.34,28.5 70.46,28.62 70.46,29.44 70.31,29.59 70,29.59 69.84,29.75 69.84,30.9 69.77,30.97 69.77,31.48 69.88,31.59 69.88,31.75 70.34,32.21 73.87,32.21 74.59,32.93 74.59,35.09 74.6,35.1 74.6,38 74.3,38.3 73.89,38.3 v1(73.32,37.73)
  BOTTOM w0.14: J3.15 v1(73.32,37.73)
DM388_CAM_DAT7: length 41.4
  TOP w0.102: 56.91,26.67 56.91,26.55 56.82,26.47 56.82,26.3 56.82,23.5 55.96,22.64 55.27,22.64 U7.B5
  TOP w0.14: v1(57.23,30.79) 57.23,30.1 56.91,29.78 56.91,26.67
  L03_SIG1 w0.119: v1(57.23,30.79) 57.23,33.12 57.84,33.73 60.9,33.73 61.02,33.85 61.02,34.98 61.22,35.18 63.6,35.18 63.72,35.3 63.72,35.34 63.84,35.46 64.08,35.46 64.2,35.34 64.2,35.3 64.32,35.18 64.56,35.18 64.67,35.3 64.67,35.34 64.79,35.46 65.03,35.46 65.15,35.34 65.15,35.3 65.27,35.18 66.14,35.18 66.7,35.74 67.21,35.74 67.29,35.66 67.29,35.43 67.42,35.31 67.74,35.31 67.82,35.39 67.82,36.2 68,36.38 68.22,36.38 68.34,36.26 68.34,35.27 68.46,35.15 68.7,35.15 68.82,35.27 68.82,36.26 68.94,36.38 71.13,36.38 71.25,36.26 71.25,35.27 71.37,35.15 71.61,35.15 71.73,35.27 71.73,36.26 71.85,36.38 72.09,36.38 72.2,36.26 72.2,35.27 72.32,35.15 72.56,35.15 72.68,35.27 72.68,36.26 72.8,36.38 73.05,36.38 73.2,36.23 73.71,36.23 v1(74.2,36.73)
  BOTTOM w0.14: J3.17 73.7,37.23 v1(74.2,36.73)
DM388_CAM_DAT8: length 41.4
  TOP w0.102: U7.K11 50.64,19.68 50.55,19.68 v1(50.51,19.73)
  L03_SIG1 w0.102: v1(50.51,19.73) 50.1,19.73 50.03,19.8 50.03,20.03 50.26,20.26 50.66,20.26 50.8,20.4 50.8,23.42 51.36,23.98 52.42,23.98 52.6,24.16 52.6,24.16 53.12,24.68 53.46,24.68 53.78,24.99 54.1,24.99 54.64,25.53 54.64,25.67 54.35,25.96 54.35,26.13 54.49,26.27 54.64,26.27 54.94,25.97 55.08,25.97 55.32,26.21 55.32,26.38 55.44,26.49 55.44,27.05 55.34,27.15 54.69,27.15 54.59,27.26 54.59,27.46 54.69,27.56 55.34,27.56 55.44,27.66 55.44,27.79
  L03_SIG1 w0.119: 55.44,27.79 55.44,30.26 55.8,30.62 56.51,30.62 57.01,31.12 57.01,33.21 57.75,33.95 60.62,33.95 60.8,34.13 60.8,35.3 61.6,36.1 61.92,36.1 62.34,35.68 66.14,35.68 66.47,36.01 66.47,36.33 66.74,36.6 72.72,36.6 72.85,36.73 v1(73.32,36.73)
  BOTTOM w0.14: J3.19 v1(73.32,36.73)
DM388_CAM_DAT9: length 41.9
  TOP w0.102: U7.E12 53.48,19.06 v1(53.23,19.31)
  L03_SIG1 w0.102: 55.94,25.38 54.69,24.13 53.93,24.13 53.06,23.27 52.81,23.27 52.48,22.93 52.48,20.67 52.07,20.26 51.89,20.26 51.67,20.04 51.67,19.21 51.85,19.03 51.85,19.03 51.96,18.91 52.83,18.91 53.05,19.13 53.05,19.13 53.23,19.31 v1(53.23,19.31)
  L03_SIG1 w0.119: 55.94,25.38 55.94,26.12 57.32,27.49 57.32,27.71 57.91,28.3 57.91,29.05 58.04,29.19 58.04,31.7 59.01,32.67 59.01,32.96 59.24,33.18 61.92,33.18 62.42,33.68 64.57,33.68 64.75,33.86 64.75,34.52 64.93,34.7 65.18,34.7 65.3,34.59 65.3,34.18 65.42,34.06 65.66,34.06 65.78,34.18 65.78,34.59 65.9,34.7 66.67,34.7 67.19,34.19 68.85,34.19 68.96,34.07 68.96,33.44 69.08,33.32 69.7,33.32 69.88,33.5 69.88,34.43 70,34.54 73.46,34.54 74.2,35.29 v1(74.2,35.73)
  BOTTOM w0.14: J3.21 73.7,36.23 v1(74.2,35.73)
DM388_CAM_DAT10: length 41.6
  TOP w0.102: v1(51.52,22.78) 51.09,22.78 50.8,22.49 50.8,20.01 U7.K10
  L03_SIG1 w0.102: v1(51.52,22.78) 51.71,22.97 51.71,23.62 51.82,23.72 52.47,23.72 52.53,23.79 52.53,23.79 53.22,24.47 53.55,24.47 53.86,24.79 54.19,24.79 55.53,26.13 55.53,26.29 55.7,26.47 55.7,26.83 55.81,26.93 56.04,26.93 56.14,27.03 56.14,27.23 56.04,27.33 55.81,27.33 55.7,27.44 55.7,27.66
  L03_SIG1 w0.119: v1(73.32,35.73) 73.32,35.05 73.2,34.93 67.99,34.93 67.87,34.81 67.87,34.56 67.75,34.44 67.51,34.44 67.39,34.56 67.39,34.81 67.27,34.93 64.38,34.93 64.26,34.81 64.26,34.08 64.14,33.96 63.9,33.96 63.78,34.08 63.78,34.81 63.66,34.93 63.43,34.93 63.31,34.81 63.31,34.08 63.19,33.96 62.95,33.96 62.83,34.08 62.83,34.81 62.71,34.93 62.46,34.93 62.36,34.82 62.36,34.42 62.15,34.21 61.46,34.21 61.34,34.1 61.34,33.62 61.23,33.5 57.93,33.5 57.53,33.11 57.53,32.22 57.79,31.97 57.79,30.52 57.67,30.4 55.89,30.4 55.7,30.21 55.7,27.66
  BOTTOM w0.14: J3.23 v1(73.32,35.73)
DM388_CAM_DAT11: length 41.8
  TOP w0.102: U7.D7 53.98,21.7 v1(53.83,21.85)
  L03_SIG1 w0.102: 56.24,24.16 55.96,23.88 54.07,23.88 53.32,23.12 53.32,22.36 v1(53.83,21.85)
  L03_SIG1 w0.119: v1(74.2,34.73) 74.2,34.28 74.09,34.16 70.87,34.16 70.73,34.02 70.73,33.22 70.61,33.1 68.6,33.1 68.48,33.22 68.48,33.69 68.36,33.81 67.43,33.81 67.31,33.69 67.31,32.99 67.19,32.87 66.95,32.87 66.83,32.99 66.83,33.69 66.71,33.81 66.01,33.81 65.89,33.69 65.89,32.99 65.77,32.87 65.53,32.87 65.41,32.99 65.41,33.69 65.29,33.81 65.05,33.81 64.93,33.69 64.93,32.91 64.81,32.79 64.57,32.79 64.45,32.91 64.45,33.26 64.33,33.38 64.09,33.38 63.97,33.26 63.97,32.91 63.85,32.79 63.61,32.79 63.5,32.91 63.5,33.26 63.38,33.38 63.14,33.38 63.02,33.26 63.02,32.91 62.9,32.79 60.9,32.79 60.37,32.26 58.92,32.26 58.31,31.66 58.31,31.41 58.43,31.29 58.86,31.29 58.98,31.17 58.98,30.96 58.84,30.81 58.43,30.81 58.31,30.69 58.31,30.46 58.43,30.34 58.76,30.34 58.88,30.22 58.88,29.98 58.76,29.86 58.43,29.86 58.31,29.74 58.31,29.15 58.13,28.96 58.13,28.21 57.54,27.62 57.54,27.36 56.24,26.06 56.24,24.16
  BOTTOM w0.14: J3.25 73.7,35.23 v1(74.2,34.73)
DM388_CAM_DAT12: length 43.3
  TOP w0.102: v1(52.62,19.88) 52.98,20.24 U7.F9
  L03_SIG1 w0.102: 56.85,21.18 56.67,21.18 56.62,21.12 56.43,21.12 55.6,20.3 53.04,20.3 v1(52.62,19.88)
  L03_SIG1 w0.119: 56.85,21.18 57.53,21.87 58.62,21.87 59.35,22.6 59.35,26.24 59.36,26.26 59.36,26.33 60.04,27.01 60.04,28.15 61.58,29.69 65.41,29.69 65.97,30.25 66.46,30.25 67.32,29.39 67.32,26.33 67.44,26.21 68.29,26.21 69.41,27.33 71.64,27.33 72.83,28.52 72.83,29.9 73.11,30.18 73.77,30.18 74.96,31.36 74.96,32.48 75.63,33.16 75.63,34.23 v1(75.09,34.78)
  BOTTOM w0.14: v1(75.09,34.78) 74.64,34.33 74.04,34.33 73.64,34.73 J3.27
DM388_CAM_DAT13: length 41.6
  TOP w0.102: v1(54.46,21.85) 54.48,21.83 U7.C7
  L03_SIG1 w0.102: 57.76,27.25 56.49,25.99 56.49,24.05 56.11,23.67 54.16,23.67 53.52,23.04 53.52,22.71 53.73,22.5 55.91,22.5 56.01,22.4 56.01,21.95 55.91,21.85 55.54,21.85 55.44,21.75 55.44,20.91 55.33,20.8 55.13,20.8 55.03,20.91 55.03,21.75 54.93,21.85 v1(54.46,21.85)
  L03_SIG1 w0.119: 57.76,27.25 57.76,27.52 58.35,28.11 58.35,28.87 61.3,31.83 61.98,31.83 62.74,31.07 64.32,31.07 64.44,31.18 64.44,31.73 65.02,32.3 66.64,32.3 69.15,29.8 69.47,29.8 69.62,29.94 69.62,30.54 69.37,30.79 69.14,30.79 68.97,30.96 68.97,31.62 69.23,31.87 69.67,31.87 70.23,32.43 73.71,32.43 74.2,32.93 v1(74.2,33.73)
  BOTTOM w0.14: v1(74.2,33.73) 73.7,34.23 J3.29
DM388_CAM_DAT14: length 41.4
  TOP w0.102: 57.31,24.62 57.31,23.05 56.38,22.12 55.76,22.12 U7.A6 ; 57.31,26.56 57.27,26.59
  TOP w0.14: v1(59.34,31.5) 57.76,29.92 57.76,28.37 57.27,27.88 57.27,26.59 ; 57.31,24.62 57.31,24.94 57.72,25.36 57.72,26.15 57.31,26.56
  L03_SIG1 w0.119: v1(73.32,33.73) 72.98,33.39 72.98,32.83 72.87,32.72 72.61,32.72 72.5,32.84 72.5,33.78 72.39,33.89 72.1,33.89 71.99,33.78 71.99,32.84 71.86,32.72 71.62,32.72 71.5,32.84 71.5,33.77 71.38,33.89 71.14,33.89 71.02,33.77 71.02,32.9 70.92,32.8 68.76,32.8 68.63,32.68 68.63,31.21 68.51,31.09 68.27,31.09 68.15,31.21 68.15,33.24 68.04,33.36 67.79,33.36 67.67,33.24 67.67,32.12 67.55,32 67.31,32 67.19,32.12 67.19,32.45 67.07,32.57 64.23,32.57 64.08,32.42 64.08,31.67 63.96,31.55 63.73,31.55 63.61,31.67 63.61,32.42 63.49,32.54 62.48,32.54 62.36,32.42 62.36,32.2 62.24,32.08 62,32.08 61.88,32.2 61.88,32.42 61.76,32.54 61.52,32.54 60.84,31.87 60.84,31.73 60.63,31.52 60.46,31.52 60.29,31.69 60.09,31.69 59.98,31.57 59.98,31.33 60.12,31.18 60.12,31.01 59.87,30.76 59.63,30.76 59.34,31.06 v1(59.34,31.5)
  BOTTOM w0.14: J3.31 v1(73.32,33.73)
DM388_CAM_DAT15: length 41.4
  TOP w0.102: v1(57.32,25.53) 57.08,25.28 57.08,23.31 56.11,22.34 U7.A5
  L03_SIG1 w0.102: 57.32,22.45 57.32,22.72 57.43,22.82 58.22,22.82 58.32,22.92 58.32,23.13 58.22,23.23 57.43,23.23 57.32,23.33 v1(57.32,25.53)
  L03_SIG1 w0.119: 57.32,22.45 57.44,22.33 58.46,22.33 58.88,22.76 58.88,26.61 59.5,27.23 59.5,28.3 61.36,30.16 65.04,30.16 65.57,30.69 66.82,30.69 67.85,29.67 67.85,27.99 68,27.84 71.52,27.84 72.27,28.6 72.27,31.49 72.39,31.61 72.64,31.61 72.77,31.47 72.77,31.13 72.89,31.01 73.12,31.01 73.24,31.13 73.24,31.49 73.36,31.61 v1(74.57,31.61)
  BOTTOM w0.14: v1(74.57,31.61) 73.95,32.23 J3.35
DM388_CAM_FLD: length 37.6
  TOP w0.14: v1(55.12,37.34) 54.62,36.84 53.99,36.84 53.99,36.84 U4.2
  L03_SIG1 w0.119: v1(55.12,37.34) 56.16,38.38 63.05,38.38 63.59,38.92 64.9,38.92 65.88,39.9 69.12,39.9 69.81,40.6 71.32,40.6 72.38,41.66 74.45,41.66 75.85,40.26 75.85,34.33 75.85,34.32 75.85,33.06 75.85,33.06 75.85,32.99 75.24,32.38 75.24,32.12 75.23,32.12 75.23,31.08 v1(74.98,30.83)
  BOTTOM w0.14: v1(74.98,30.83) 74.52,30.83 74.28,30.58 73.87,30.58 73.73,30.73 J3.41
DM388_CAM_FLD_UT_CTSN: length 41.5
  TOP w0.102: v1(51.18,22.3) 51.18,22.1 51.01,21.92 51.01,20.31 U7.J10
  TOP w0.14: v1(55.1,38.23) 54.71,37.84 53.99,37.84 53.99,37.84 U4.4
  L03_SIG1 w0.102: v1(51.18,22.3) 51,22.12 51,19.34 51.11,19.24 51.34,19.24 51.46,19.37 51.46,20.45 51.57,20.55 52.04,20.55 52.18,20.69 52.18,20.83 52.08,20.93 51.41,20.93 51.31,21.03 51.31,21.21 51.44,21.33 52.11,21.33 52.21,21.43 52.21,21.92 52.11,22.02 51.87,22.02 51.74,22.15 51.74,22.32 51.85,22.42 52.11,22.42 52.21,22.53 52.21,23.1 52.58,23.47 52.98,23.47 53.84,24.33 54.03,24.33 54.44,24.74 54.58,24.74 54.73,24.6 54.87,24.6 55.01,24.74 55.01,24.88 54.87,25.03 54.87,25.17 55.01,25.32 55.16,25.32 55.3,25.17 55.44,25.17 55.59,25.32 55.59,25.46 55.44,25.6 55.44,25.75 55.73,26.04 55.73,26.21 56.89,27.37 56.89,27.54
  L03_SIG1 w0.119: v1(57.33,29.41) 57.64,29.72 57.64,29.93 57.46,30.11 56.1,30.11 55.98,29.99 55.98,29.68 56.11,29.54 56.72,29.54 56.84,29.42 56.84,29.17 56.72,29.05 56.05,29.05 55.93,28.93 55.93,28.7 56.05,28.58 56.79,28.58 56.91,28.46 56.91,28.18 56.8,28.07 56.09,28.07 56,27.98 56,27.77 56.11,27.66 56.77,27.66 56.89,27.54
  L06_SIG2 w0.119: v1(55.1,38.23) 55.96,37.36 55.96,36.9 57.65,35.22 57.65,29.72 v1(57.33,29.41)
DM388_CAM_HS: length 31.7
  TOP w0.102: U7.D5 53.9,22.41 53.9,22.8 53.93,22.83 v1(53.93,22.88)
  L03_SIG1 w0.102: v1(53.93,22.88) 56.06,22.88 56.9,23.72 56.9,25.68 57.41,26.19 57.74,26.19
  L03_SIG1 w0.119: v1(70.9,30.73) 71.93,30.73 72.05,30.62 72.05,28.69 71.42,28.06 68.34,28.06 68.07,28.33 68.07,29.76 66.92,30.91 65.35,30.91 64.82,30.38 61.09,30.38 59.23,28.51 59.23,28.42 59.23,27.41 58.01,26.19 57.74,26.19
  BOTTOM w0.14: J3.37 71.1,31.73 70.9,31.52 v1(70.9,30.73)
DM388_CAM_PCLK: length 29.6
  TOP w0.14: R142.2 55.3,39.04 54.6,38.34 v1(54.11,38.34) U4.5
  L06_SIG2 w0.102: 57.05,28.93 v1(57.36,28.63)
  L06_SIG2 w0.119: 57.05,28.93 56.82,29.17 56.82,34.27 54.66,36.42 54.66,37.78 v1(54.11,38.34) ; v1(71.3,29.85) 70.86,29.85 70.66,29.64 66.74,29.64 66.66,29.57 v1(66.22,29.57)
  BOTTOM w0.102: 57.66,28.93 v1(57.36,28.63)
  BOTTOM w0.14: J3.43 71.68,30.23 v1(71.3,29.85) ; v1(66.22,29.57) 63.58,29.57 63.07,30.07 60.43,30.07 59.59,29.24 57.97,29.24 57.66,28.93
DM388_CAM_PCLK_UT_RTSN: length 21
  TOP w0.102: 56.32,26.52 56.39,26.45 56.39,23.83 55.61,23.04 55.27,23.04 U7.B3
  TOP w0.14: R142.1 54.83,40.06 v1(54.11,39.34) U4.7 ; 56.32,26.52 56.32,31.59 56.34,31.6 v1(56.34,32.06)
  L06_SIG2 w0.119: v1(56.34,32.06) 56.34,34.29 53.65,36.98 53.65,38.88 v1(54.11,39.34)
DM388_CAM_RESET: length 46.4
  TOP w0.102: U7.H16 52.08,16.84 52.35,17.11 v1(52.35,17.28)
  L03_SIG1 w0.102: v1(52.35,17.28) 52.35,17.55 52.33,17.57 52.33,18.01 52.58,18.26 52.75,18.26 52.99,18.5 53,18.5 53.13,18.64 54.61,18.64 56.09,20.11 57.31,20.11
  L03_SIG1 w0.119: 57.31,20.11 57.74,20.11 60.1,22.47 60.1,24.92 60.6,25.42 60.6,27.94 61.89,29.24 65.95,29.24 66.87,28.31 66.87,21.82 67.04,21.65 67.99,21.65 68.11,21.77 68.11,25.41 69.59,26.89 71.82,26.89 74.44,29.52 v1(74.88,29.52)
  BOTTOM w0.14: v1(74.88,29.52) 74.59,29.23 J3.47
DM388_CAM_SHUTTER: length 44
  TOP w0.102: v1(52.71,17.73) 52.4,18.04 52.38,18.04 52.08,18.34 U7.H13
  L03_SIG1 w0.102: v1(52.71,17.73) 52.71,17.94 53.07,18.3 53.08,18.3 53.21,18.43 54.7,18.43 56.11,19.84 57.31,19.84
  L03_SIG1 w0.119: v1(74.81,27.66) 74.48,27.33 73.59,27.33 72.93,26.67 70.49,26.67 68.33,24.51 68.33,21.46 68.22,21.34 66.77,21.34 66.65,21.46 66.65,28.22 65.86,29.02 63.53,29.02 62.67,28.16 62.67,26.68 60.4,24.41 60.4,22.39 57.85,19.84 57.31,19.84
  BOTTOM w0.14: v1(74.81,27.66) 74.45,28.02 73.7,28.02 73.49,28.23 72.5,28.23
DM388_CAM_STROBE: length 44.5
  TOP w0.102: U7.F13 52.98,18.13 53.17,17.93 v1(53.24,17.93)
  L03_SIG1 w0.102: v1(53.24,17.93) 53.54,18.23 55.62,18.23 56.96,19.57 57.31,19.57
  L03_SIG1 w0.119: v1(74.07,28.5) 74.58,28.5 75.24,27.84 75.24,27.33 74.98,27.08 73.71,27.08 71.56,24.92 69.93,24.92 68.56,23.54 68.56,21.23 68.44,21.11 66.52,21.11 66.4,21.23 66.4,28.11 65.75,28.75 63.66,28.75 62.95,28.04 62.95,26.57 60.81,24.43 60.81,21.28 59.1,19.57 57.31,19.57
  BOTTOM w0.14: v1(74.07,28.5) 73.62,28.5 73.39,28.73 J3.49
DM388_CAM_VS: length 41.4
  TOP w0.102: U7.H9 51.98,19.95 v1(52.05,19.88)
  L03_SIG1 w0.102: 57.24,21.88 56.3,21.88 56.08,21.66 56.08,21.05 55.55,20.52 54.44,20.52 54.34,20.63 54.34,21.34 54.23,21.44 54.03,21.44 53.93,21.34 53.93,20.63 53.83,20.52 53.62,20.52 53.52,20.63 53.52,21.34 53.42,21.44 53.22,21.44 53.12,21.34 53.12,20.63 53.01,20.52 52.69,20.52 v1(52.05,19.88)
  L03_SIG1 w0.119: v1(73.98,31.04) 73.54,31.04 72.5,30 72.5,28.51 71.54,27.55 68.14,27.55 68.03,27.44 68.03,26.59 67.91,26.47 67.71,26.47 67.59,26.59 67.59,29.52 66.64,30.47 65.81,30.47 65.25,29.91 61.49,29.91 59.77,28.19 59.77,27.12 59.14,26.48 59.14,26.34 59.12,26.33 59.12,22.69 58.53,22.09 57.44,22.09 57.24,21.88
  BOTTOM w0.14: v1(73.98,31.04) 73.89,31.04 73.7,31.23 J3.39
DM388_CAM_WEN: length 41.9
  TOP w0.102: v1(52.1,15.89) 51.98,16.01 U7.H17
  L03_SIG1 w0.102: 57.31,20.4 56.09,20.4 54.53,18.84 53.04,18.84 52.91,18.71 52.9,18.71 52.71,18.52 51.79,18.52 51.32,18.04 51.32,16.67 v1(52.1,15.89)
  L03_SIG1 w0.119: v1(73.32,29.73) 73.32,28.7 71.73,27.11 69.5,27.11 67.89,25.5 67.89,24.64 67.72,24.47 67.21,24.47 67.1,24.59 67.1,29.3 66.42,29.98 66.03,29.98 65.51,29.46 61.74,29.46 60.31,28.04 60.31,26.89 59.57,26.15 59.57,22.51 57.46,20.4 57.31,20.4
  BOTTOM w0.14: J3.45 v1(73.32,29.73)
DM388_CSI_DX0: length 51.7
  TOP w0.102: v1(44.97,27.26) 44.76,27.04 44.76,25.91 44.68,25.83 44.68,24.19 44.73,24.14 44.73,24.13 44.98,23.89 U7.AB2
  L03_SIG1 w0.102: v1(9.91,26.62) 9.91,26.64 10.04,26.77 11.36,26.77 11.47,26.67 11.47,24.91 11.76,24.62 12.24,24.62 12.53,24.91 12.53,27.02 12.64,27.13 13.03,27.13 13.14,27.03 13.14,26.59 13.46,26.27 14.34,26.27 14.34,26.26 15.46,26.26 15.75,26.56 15.75,27.17 15.85,27.27 16.98,27.27 17.08,27.17 17.08,26.37 17.56,25.89 18.23,25.89 18.72,26.38 26.45,26.38 26.65,26.19 28.38,26.19 29.12,26.92 31.36,26.92 32.58,28.14 33.14,28.14 33.32,27.96 36.46,27.96 36.48,27.99 37.39,27.99 37.55,28.14 40.71,28.14 41.75,27.1 42.35,27.1 42.65,27.41 42.65,28.04 42.75,28.14 43.08,28.14 43.18,28.04 43.18,26.68 43.48,26.38 44.45,26.38 44.73,26.66 44.73,27.02 v1(44.97,27.26)
  BOTTOM w0.102: J4.38 10.59,26.83 10.48,26.94 9.95,26.94 9.91,26.9 v1(9.91,26.62)
DM388_CSI_DX1: length 51.9
  TOP w0.102: U7.AA1 45.48,24.58 45.45,24.61 45.45,26.52 45.53,26.59 45.53,26.6 45.83,26.9 45.83,27.91 v1(45.99,28.08)
  L03_SIG1 w0.102: v1(8.01,28.68) 8.21,28.88 8.21,29.17 8.31,29.27 8.31,30.79 8.6,31.08 9.39,31.08 9.99,30.48 9.99,29.49 9.99,28.78 10.09,28.68 25.76,28.68 26.45,29.36 32.15,29.36 33.34,30.56 37.26,30.56 38.46,29.36 44.99,29.36 45.78,28.57 45.78,28.28 v1(45.99,28.08)
  BOTTOM w0.102: v1(8.01,28.68) 8.21,28.49 8.21,28.24 8.47,27.97 9.27,27.97 9.74,28.44 10.48,28.44 10.59,28.33 11.27,28.33
DM388_CSI_DX2: length 51.4
  TOP w0.102: v1(46.57,28.6) 46.74,28.44 46.74,27.15 45.77,26.19 45.77,24.14 U7.AA2
  L03_SIG1 w0.102: v1(13.53,29.62) 13.39,29.76 13.39,29.95 13.49,30.05 14.91,30.05 15.29,30.43 15.44,30.43 15.54,30.33 15.54,29.51 15.83,29.21 16.31,29.21 16.6,29.51 16.6,30.33 16.71,30.43 20.19,30.43 21.33,29.29 22.15,29.29 22.44,29.58 22.44,31.22 22.55,31.32 22.75,31.32 22.85,31.22 22.85,29.58 23.15,29.29 24.78,29.29 25.42,29.92 29.48,29.92 30.67,31.12 30.9,31.12 31,31.01 31,30.55 31.3,30.25 31.77,30.25 32.07,30.55 32.07,31.01 32.17,31.12 37.7,31.12 38,30.81 38.89,29.92 46.26,29.92 46.76,29.42 46.76,28.79 v1(46.57,28.6)
  BOTTOM w0.102: J4.50 11.96,29.83 12.07,29.94 13.21,29.94 v1(13.53,29.62)
DM388_CSI_DX3: length 51.3
  TOP w0.102: v1(47.55,27.56) 47.55,27.12 47.7,26.98 47.7,26.8 46.24,25.34 46.24,24.9 46.2,24.86 46.2,24.22 46.48,23.94 U7.W2
  L03_SIG1 w0.102: v1(13.53,32.12) 13.85,32.44 14.18,32.44 14.56,32.06 15.45,32.06 15.75,32.36 15.75,33 15.85,33.1 16.2,33.1 16.34,32.96 16.34,31.62 16.64,31.32 17.28,31.32 17.58,31.62 17.58,32.91 17.77,33.1 18.62,33.1 18.72,33 18.72,32.5 19.04,32.18 19.99,32.18 20.91,33.1 22.23,33.1 24.08,31.24 29.26,31.24 30.18,32.16 37.93,32.16 39.28,30.81 47.54,30.81 47.88,30.48 47.88,30.02 47.87,30.02 47.73,29.88 47.73,27.73 v1(47.55,27.56)
  BOTTOM w0.102: J4.58 11.96,32.33 12.07,32.44 13.21,32.44 v1(13.53,32.12)
DM388_CSI_DX4: length 51.7
  TOP w0.102: U7.V1 47.07,24.43 47.07,25.21 48.77,26.91 48.77,28.15 v1(48.58,28.34)
  L03_SIG1 w0.102: v1(48.58,28.34) 48.9,28.65 48.9,29.53 48.77,29.66 48.77,30.84 47.43,32.18 43.69,32.18 43.21,31.7 39.81,31.7 38.03,33.48 36.94,33.48 36.52,33.06 29.24,33.06 28.77,32.59 27.33,32.59 25.89,34.04 9.94,34.04 9.92,34.05 9.69,34.05 9.53,33.88 9.53,33.63 9.65,33.51 9.8,33.51 v1(9.91,33.62)
  BOTTOM w0.102: v1(9.91,33.62) 9.91,33.9 9.95,33.94 10.48,33.94 10.59,33.83 J4.64
DM388_CSI_DY0: length 51.7
  TOP w0.102: v1(44.26,27.26) 44.48,27.04 U7.AC2
  L03_SIG1 w0.102: v1(9.91,27.53) 9.74,27.53 9.63,27.42 9.63,27.23 9.76,27.1 11.5,27.1 11.8,26.81 11.8,25.05 11.9,24.95 12.1,24.95 12.2,25.05 12.2,27.16 12.5,27.46 13.17,27.46 13.47,27.16 13.47,26.73 13.6,26.6 14.47,26.6 14.48,26.59 15.32,26.59 15.42,26.7 15.42,27.31 15.72,27.6 17.12,27.6 17.41,27.31 17.41,26.51 17.7,26.22 18.1,26.22 18.58,26.71 26.59,26.71 26.78,26.52 28.24,26.52 28.98,27.26 31.22,27.26 32.44,28.47 33.28,28.47 33.46,28.29 36.32,28.29 36.35,28.32 37.25,28.32 37.41,28.47 40.85,28.47 41.89,27.43 42.21,27.43 42.32,27.54 42.32,28.18 42.62,28.47 43.22,28.47 43.51,28.18 43.51,26.81 43.62,26.71 44.32,26.71 44.4,26.8 44.4,27.12 v1(44.26,27.26)
  BOTTOM w0.102: J4.40 10.59,27.33 10.48,27.22 10.06,27.22 9.91,27.37 v1(9.91,27.53)
DM388_CSI_DY1: length 51.8
  TOP w0.102: U7.AB1 45.25,24.61 45.25,26.72 45.55,27.02 45.55,27.81 v1(45.28,28.08)
  L03_SIG1 w0.102: v1(8.98,28.68) 8.98,28.38 8.88,28.28 8.64,28.28 8.54,28.38 8.54,29.03 8.64,29.13 8.64,30.65 8.74,30.75 9.25,30.75 9.66,30.34 9.66,28.64 9.95,28.35 25.9,28.35 26.58,29.03 32.29,29.03 33.48,30.23 37.13,30.23 38.32,29.03 44.85,29.03 45.45,28.43 45.45,28.25 v1(45.28,28.08)
  BOTTOM w0.102: v1(8.98,28.68) 8.61,28.68 8.49,28.56 8.49,28.35 8.59,28.25 9.16,28.25 9.62,28.72 10.48,28.72 10.59,28.83 J4.46
DM388_CSI_DY2: length 51.4
  TOP w0.102: U7.Y2 45.98,26 46.97,26.99 46.97,28.28 46.97,28.29 46.97,28.34 v1(47.28,28.65)
  L03_SIG1 w0.102: v1(47.28,28.65) 47.09,28.83 47.09,29.55 46.39,30.25 39.03,30.25 38.33,30.95 38.33,30.95 37.84,31.45 32.03,31.45 31.74,31.15 31.74,30.68 31.64,30.58 31.43,30.58 31.33,30.68 31.33,31.15 31.04,31.45 30.53,31.45 29.34,30.25 25.28,30.25 24.65,29.62 23.28,29.62 23.18,29.72 23.18,31.35 22.89,31.65 22.41,31.65 22.11,31.35 22.11,29.72 22.01,29.62 21.47,29.62 20.32,30.76 16.57,30.76 16.27,30.47 16.27,29.64 16.17,29.54 15.97,29.54 15.87,29.64 15.87,30.46 15.57,30.76 15.16,30.76 14.78,30.38 13.68,30.38 v1(13.53,30.53)
  BOTTOM w0.102: v1(13.53,30.53) 13.21,30.22 12.07,30.22 11.96,30.33 J4.52
DM388_CSI_DY3: length 51.3
  TOP w0.102: U7.W1 46.48,24.86 46.44,24.9 46.44,25.25 47.58,26.4 47.61,26.4 47.98,26.77 47.98,27.27 v1(48.26,27.56)
  L03_SIG1 w0.102: v1(48.26,27.56) 48.1,27.72 48.1,29.78 48.21,29.89 48.21,30.61 47.68,31.14 39.41,31.14 38.07,32.49 30.04,32.49 29.13,31.57 24.22,31.57 22.36,33.43 20.77,33.43 19.86,32.51 19.18,32.51 19.05,32.64 19.05,33.13 18.76,33.43 17.63,33.43 17.25,33.05 17.25,31.76 17.14,31.65 16.78,31.65 16.67,31.76 16.67,33.1 16.34,33.43 15.71,33.43 15.42,33.13 15.42,32.49 15.31,32.39 14.69,32.39 14.31,32.77 13.79,32.77 v1(13.53,33.03)
  BOTTOM w0.102: v1(13.53,33.03) 13.21,32.72 12.07,32.72 11.96,32.83 J4.60
DM388_CSI_DY4: length 51.7
  TOP w0.102: v1(49.29,28.34) 49.05,28.09 49.05,26.8 48.7,26.45 48.6,26.45 47.27,25.13 47.27,24.14 U7.V2
  L03_SIG1 w0.102: v1(9.91,34.53) 10.08,34.37 26.02,34.37 27.47,32.92 28.63,32.92 29.1,33.39 36.38,33.39 36.81,33.81 38.17,33.81 39.95,32.03 43.07,32.03 43.56,32.51 47.56,32.51 49.1,30.98 49.1,29.8 49.23,29.67 49.23,28.69 49.29,28.63 v1(49.29,28.34)
  BOTTOM w0.102: v1(9.91,34.53) 9.91,34.37 10.06,34.22 10.48,34.22 10.59,34.33 J4.66
DM388_DDR0_A0: length 49.9
  TOP w0.102: U6.N3 v1(24.31,21.75) ; U7.AL24 40.15,12.84 v1(39.96,13.03) ; U8.N3 v1(24.31,11.59)
  L06_SIG2 w0.102: v1(24.31,11.59) 24.31,11.85 24.7,12.23 24.7,14.57 24.61,14.66 24.33,14.66 24.24,14.75 24.24,14.88 24.33,14.97 24.61,14.97 24.7,15.06 24.7,18.01 24.17,18.53 24.17,19.39 24.07,19.49 23.88,19.49 23.78,19.59 23.78,19.8 23.88,19.9 24.21,19.9 24.31,20 24.31,20.2 24.21,20.3 23.88,20.3 23.78,20.41 23.78,20.61 23.88,20.71 24.21,20.71 24.31,20.81 v1(24.31,21.75)
  BOTTOM w0.102: v1(24.31,21.75) 24.03,21.46 23.91,21.46 23.12,20.68 22.36,20.68 21.71,20.03 RA7.8 ; v1(24.31,11.59) 24.7,11.97 24.7,12.51 24.96,12.77 25.6,12.77 25.69,12.86 25.69,13.1 25.78,13.19 25.9,13.19 25.99,13.1 25.99,12.86 26.08,12.77 26.12,12.77 26.3,12.6 26.3,12.09 26.41,11.97 27.9,11.97 27.98,11.88 27.98,11.46 28.07,11.37 28.2,11.37 28.29,11.46 28.29,11.88 28.38,11.97 29.63,11.97 29.72,11.88 29.72,11.46 29.81,11.37 29.93,11.37 30.02,11.46 30.02,11.88 30.11,11.97 30.24,11.97 30.33,11.88 30.33,11.46 30.41,11.37 30.54,11.37 30.63,11.46 30.63,11.88 30.72,11.97 34.07,11.97 34.43,11.61 35.39,11.61 36.81,13.03 39.22,13.03 40.07,12.18 40.73,12.18 41.2,12.65 41.51,12.65 41.6,12.74 41.6,12.84 41.69,12.93 41.82,12.93 41.91,12.84 41.91,12.74 41.99,12.65 42.12,12.65 42.21,12.74 42.21,12.84 42.3,12.93 42.43,12.93 42.51,12.84 42.51,12.74 42.6,12.65 42.89,12.65 42.98,12.74 42.98,12.84 43.06,12.93 43.19,12.93 43.28,12.84 43.28,12.74 43.37,12.65 43.69,12.65 43.79,12.75 43.79,13.06 43.69,13.16 43.33,13.16 43.24,13.25 43.24,13.34 43.15,13.43 43.02,13.43 42.93,13.34 42.93,13.25 42.84,13.16 40.52,13.16 40.39,13.03 v1(39.96,13.03)
